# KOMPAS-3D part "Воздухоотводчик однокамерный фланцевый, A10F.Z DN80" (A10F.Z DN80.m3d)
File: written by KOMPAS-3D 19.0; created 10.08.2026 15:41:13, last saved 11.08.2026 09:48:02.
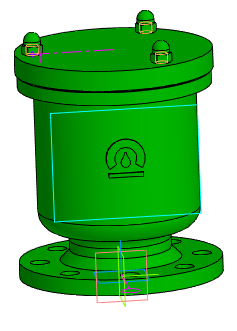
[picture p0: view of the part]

Document properties: Автор: Энергия; Полное имя файла: Z:\3.Личные\kachalov\001_3d для проектировщиков\x.x Тип A10F.Z Воздухоотводчик однокамерный фланцевый\A10F.Z DN80.m3d

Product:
- Part/product: Воздухоотводчик однокамерный фланцевый  | designation A10F.Z DN80
    Масса: 28.6796
  - Component [standard]: Гайка М12-6H (S18) ГОСТ 11860-85  | qty 3  | Масса: 0.02606; Раздел спецификации: Стандартные изделия; Рассекать на разрезах: no; source file: C:\Program Files\ASCON\KOMPAS-3D v19\Libs\PARTLib\DATA\vault\Methods\Kompas\3D\PLib_Blind_Nut_type1_900.m3d

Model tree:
1. Эскиз:1
2. Элемент вращения:1
     Угол 1 = 360
3. Скругление:1  (with: Элемент вращения:1)
     Радиус = 10
4. Фаска:1  (with: Элемент вращения:1)
     Угол = 45; Длина 1 = 10; Длина 2 = 10
5. Эскиз:2  (with: Элемент вращения:1)
6. Точка:1
     Y = -80; Z = 228; Координата Y = -80; Координата Z = 228
7. Массив по концентрической сетке:1  (with: Элемент вращения:1)  (3 pattern instances)
     Шаг 2 = 360
8. Эскиз:3  (with: Элемент вращения:1)
9. Элемент выдавливания:1  (with: Элемент вращения:1, Массив по концентрической сетке:1, Эскиз:3)  (8 pattern instances)
     Расстояние 2 = 16; N 1 = 1; Шаг 1 = 10; Шаг 2 = 360; Номер 1 = 1
10. Касательная плоскость:1  (with: Элемент вращения:1)
11. Эскиз:4
12. Элемент выдавливания:2  (with: Элемент вращения:1)  (labels: Фаска наружная:1)
     Расстояние 1 = 1; Ориентация = 2

Expressions: Dn/2; D2/2; D/2; B/2; D1/2; H/2
Referenced files in C:\Program Files\ASCON\KOMPAS-3D v19\Libs\PARTLib\DATA\vault\Methods\Kompas\3D\: PLib_Blind_Nut_type1_900.m3d
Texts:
  A10F.Z DN80
  Гайка М12-6H (S18) ГОСТ 11860-85 (1)
  foc1
  foc2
